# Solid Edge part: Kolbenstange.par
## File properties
Username: ahadarics
Dokumentum tartalom típus: 0
Author: ahadarics
Last saved by: ahadarics
Revision: 87
Sűrűség: 0,000 kg/m^3
Pontosság: 0,990
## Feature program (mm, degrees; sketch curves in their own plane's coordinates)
base feature "unnamed BaseFeature 1"
sketch for "unnamed Protrusion 1" plane through (46.75, 0, 0) normal (1, 0, 0) x-axis (0, -1, 0)
  circle centre (0, 0) radius 6
extrude "unnamed Protrusion 1" add finite 27 along -normal
thread "Menet_1"  ThreadDepth = 16 mm
chamfer "Letörés_2" setback 0.4
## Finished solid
Body 1: solid body, 13 faces, 23 edges, 12 vertices.
  Faces by surface: plane 9, cylinder 3, cone 1
  Edges by curve: line 12, circle 11
Bounding box of the edges (mm): 395.500 x 12.000 x 12.000, from (-348.75, -6, -6) to (46.75, 6, 6).
Cylindrical faces by radius (mm): R3 x2, R6 x1
Conical faces (half-angle, radius in mm at the cone's reference point): 45 deg R2.6 x1
Planar faces by outward normal: +x 3, +z 1, -x 4, -z 1
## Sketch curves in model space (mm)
circle centre (46.75, 0, 0) radius 6
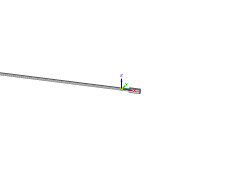
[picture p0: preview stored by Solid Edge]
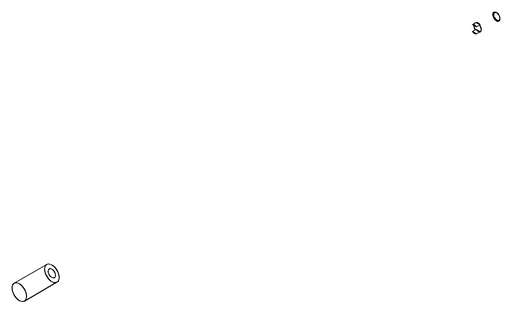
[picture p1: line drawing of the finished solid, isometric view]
